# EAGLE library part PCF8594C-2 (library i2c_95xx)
512 x 8-Bit CMOS EEPROM with I²C Bus Interface
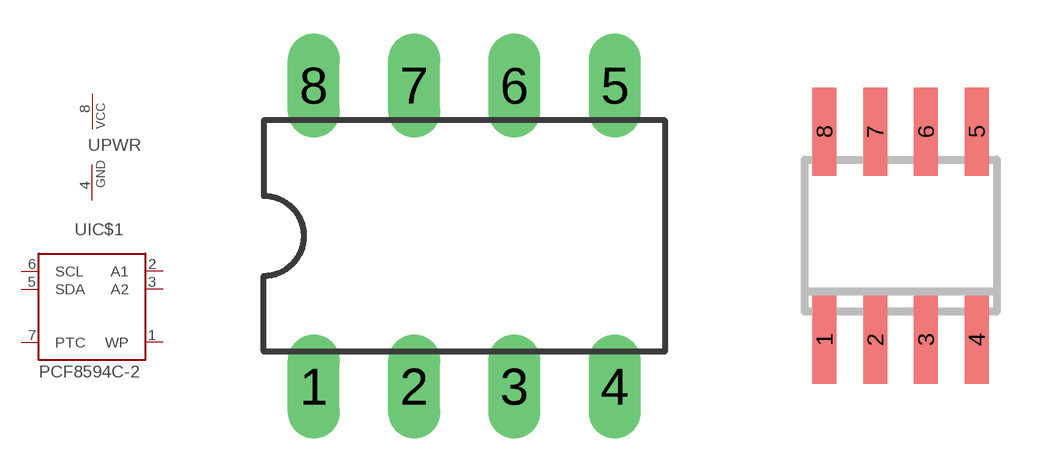
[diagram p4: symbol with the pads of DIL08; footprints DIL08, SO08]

Designator prefix -; gates IC$1=PCF8594 PWR=PWRN

## PCF8594C-2P/02  [DIL08]
1  IC$1:WP  in
2  IC$1:A1  in
3  IC$1:A2  in
4  PWR:GND  pwr
5  IC$1:SDA
6  IC$1:SCL  in
7  IC$1:PTC
8  PWR:VCC  pwr

## PCF8594C-2T/02  [SO08]
Pads as for DIL08

## Footprint DIL08 (pad centres in mm)
drill 0.813 long: 1 -3.81,-3.81; 2 -1.27,-3.81; 3 1.27,-3.81; 4 3.81,-3.81; 5 3.81,3.81; 6 1.27,3.81; 7 -1.27,3.81; 8 -3.81,3.81

## Footprint SO08 (pad centres in mm)
smd 0.6 x 2.2: 1 -1.905,-2.6; 2 -0.635,-2.6; 3 0.635,-2.6; 4 1.905,-2.6; 5 1.905,2.6; 6 0.635,2.6; 7 -0.635,2.6; 8 -1.905,2.6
